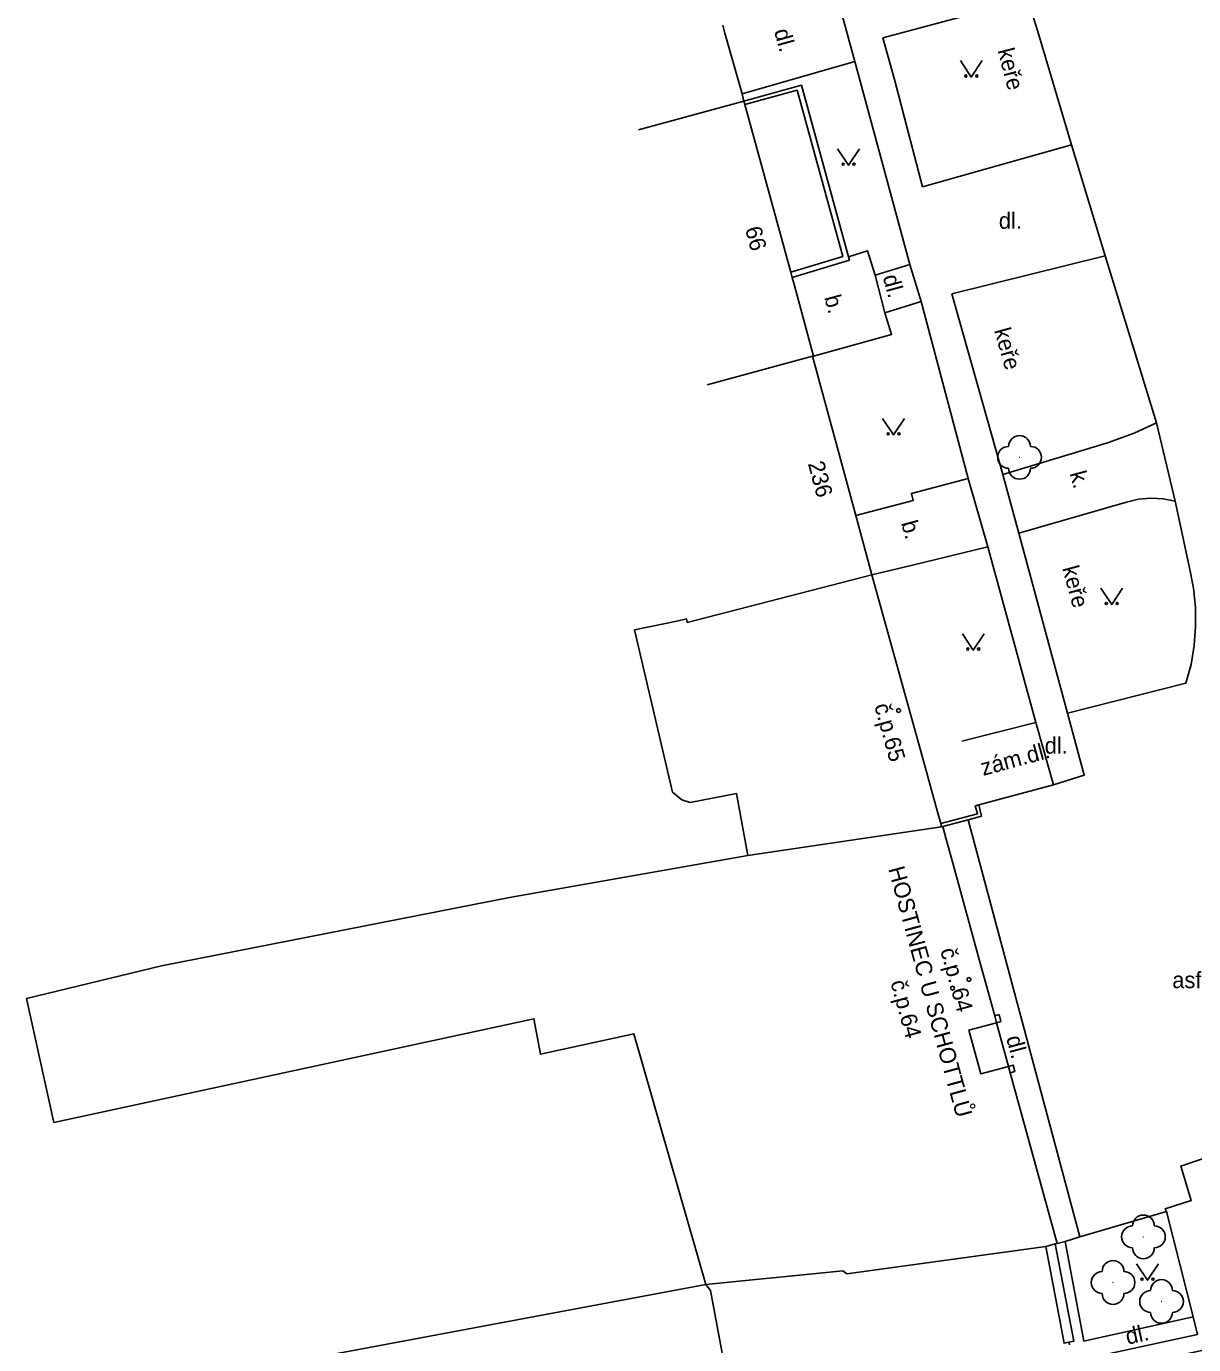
# Model space of a CAD drawing. Extents: x -577457 to -568404, y -1208466 to -1201387.
# Drawn here: x -575435.2 to -575381.8, y -1204135.5 to -1204075.1 of the extents above; entities that cross this region are included whole.
import ezdxf

# ---------------------------------------------------------------- set-up
doc = ezdxf.new("R2010")
doc.units = 0
for name, color, linetype in [('BUDOVY_MĚŘ', 7, 'Continuous'), ('BUDOVY_NEMĚŘ', 7, 'Continuous'), ('POMOC_POPIS', 7, 'Continuous'), ('ROZHRANÍ_PLOCH', 7, 'Continuous'), ('ZELEŇ', 7, 'Continuous'), ('ZN_BUDOV', 7, 'Continuous'), ('ZN_DOPLŇKOVÉ', 7, 'Continuous'), ('ZN_KULTUR', 7, 'Continuous'), ('Č_POPIS_ORIENT', 7, 'Continuous')]:
    doc.layers.add(name, color=color, linetype=linetype)

msp = doc.modelspace()

# ---------------------------------------------------------------- linework, layer by layer
at = {"layer": 'BUDOVY_MĚŘ'}
for points in [[(-575403.21, -1204075.42), (-575403.31, -1204075.05)], [(-575407.17, -1204079.85), (-575402.34, -1204078.53)], [(-575402.43, -1204078.2), (-575402.46, -1204078.09)], [(-575402.34, -1204078.53), (-575402.43, -1204078.2)], [(-575402.3, -1204078.69), (-575402.34, -1204078.53)], [(-575400.2, -1204086.37), (-575402.3, -1204078.69)], [(-575400.13, -1204086.61), (-575400.2, -1204086.37)], [(-575400.06, -1204086.87), (-575400.13, -1204086.61)], [(-575399.15, -1204090.21), (-575399.37, -1204089.42)], [(-575404.02, -1204091.53), (-575399.2, -1204090.22)], [(-575399.2, -1204090.22), (-575399.15, -1204090.21)], [(-575397.22, -1204097.51), (-575399.2, -1204090.22)], [(-575396.48, -1204100.23), (-575396.54, -1204100)], [(-575396.44, -1204100.39), (-575396.48, -1204100.23)], [(-575394.23, -1204108.36), (-575396.44, -1204100.39)], [(-575393.33, -1204111.62), (-575393.48, -1204111.09)], [(-575393.29, -1204111.77), (-575393.33, -1204111.62)], [(-575393.24, -1204111.76), (-575393.29, -1204111.77)], [(-575393.08, -1204112.34), (-575393.24, -1204111.76)], [(-575391.52, -1204118.02), (-575392.75, -1204113.54)], [(-575391.24, -1204119.06), (-575391.52, -1204118.02)], [(-575390.86, -1204120.43), (-575391.24, -1204119.06)], [(-575390.78, -1204120.74), (-575390.86, -1204120.43)], [(-575390.23, -1204122.74), (-575390.78, -1204120.74)], [(-575390.15, -1204123.04), (-575390.23, -1204122.74)], [(-575388, -1204130.85), (-575390.15, -1204123.04)], [(-575388.52, -1204130.99), (-575388.09, -1204130.87)], [(-575388.09, -1204130.87), (-575388, -1204130.85)]]:
    msp.add_lwpolyline(points, dxfattribs=at)
at = {"layer": 'BUDOVY_NEMĚŘ'}
for points in [[(-575405.42, -1204102.35), (-575404.97, -1204102.25), (-575404.94, -1204102.41), (-575396.48, -1204100.23)], [(-575402.17, -1204113.08), (-575402.68, -1204110.25), (-575404.81, -1204110.66), (-575405.19, -1204110.53), (-575405.61, -1204110.19), (-575407.35, -1204102.75), (-575405.42, -1204102.35)], [(-575393.29, -1204111.77), (-575402.17, -1204113.08)], [(-575402.17, -1204113.08), (-575413.08, -1204115.01), (-575429.01, -1204118.14), (-575435.2, -1204119.64), (-575433.94, -1204125.31), (-575411.96, -1204120.56), (-575411.66, -1204122.19), (-575407.38, -1204121.25), (-575404.09, -1204132.73)], [(-575404.09, -1204132.73), (-575397.82, -1204132.1), (-575397.63, -1204132.25), (-575388.52, -1204130.99)], [(-575404.09, -1204132.73), (-575403.88, -1204133.01), (-575402.82, -1204138.65), (-575402.57, -1204140.06), (-575409.22, -1204141.08), (-575409.48, -1204139.36), (-575426.48, -1204142.06), (-575425.1, -1204148.33), (-575429.23, -1204149.24), (-575430.17, -1204145.04), (-575431.67, -1204138.32), (-575427.47, -1204137.4), (-575421.87, -1204136.06), (-575404.09, -1204132.73)]]:
    msp.add_lwpolyline(points, dxfattribs=at)
at = {"layer": 'ROZHRANÍ_PLOCH'}
for points in [[(-575397.26, -1204076.72), (-575398.1, -1204073.63)], [(-575395.98, -1204075.64), (-575389.34, -1204073.85)], [(-575389.34, -1204073.85), (-575388.85, -1204075.45), (-575387.34, -1204080.54)], [(-575394.16, -1204082.46), (-575395.45, -1204077.54), (-575395.98, -1204075.64)], [(-575397.26, -1204076.72), (-575402.43, -1204078.2)], [(-575397.26, -1204076.72), (-575394.75, -1204086.02)], [(-575394.16, -1204082.46), (-575387.34, -1204080.54)], [(-575387.34, -1204080.54), (-575385.8, -1204085.62)], [(-575396.33, -1204086.5), (-575396.69, -1204085.39), (-575397.55, -1204085.66)], [(-575392.82, -1204087.36), (-575385.8, -1204085.62)], [(-575385.8, -1204085.62), (-575383.45, -1204093.27)], [(-575396.33, -1204086.5), (-575394.75, -1204086.02)], [(-575394.75, -1204086.02), (-575394.23, -1204087.71)], [(-575395.89, -1204088.23), (-575396.33, -1204086.5)], [(-575390.49, -1204095.63), (-575392.82, -1204087.36)], [(-575399.15, -1204090.21), (-575395.58, -1204089.22), (-575395.89, -1204088.23)], [(-575395.89, -1204088.23), (-575394.23, -1204087.71)], [(-575394.23, -1204087.71), (-575392.08, -1204095.82)], [(-575383.45, -1204093.27), (-575384.47, -1204093.74), (-575385.52, -1204094.13), (-575385.7, -1204094.19), (-575390.49, -1204095.63)], [(-575383.45, -1204093.27), (-575382.59, -1204096.86)], [(-575392.08, -1204095.82), (-575394.67, -1204096.5), (-575394.59, -1204096.82), (-575397.22, -1204097.51)], [(-575392.08, -1204095.82), (-575391.17, -1204098.94)], [(-575390.49, -1204095.63), (-575389.75, -1204098.32)], [(-575389.75, -1204098.32), (-575384.83, -1204096.9), (-575384.27, -1204096.77), (-575383.71, -1204096.72), (-575383.14, -1204096.75), (-575382.59, -1204096.86)], [(-575387.53, -1204106.56), (-575382.1, -1204105.19), (-575381.87, -1204104.34), (-575381.73, -1204103.47), (-575381.66, -1204102.6), (-575381.67, -1204101.72), (-575381.76, -1204100.84), (-575381.93, -1204099.98), (-575382.59, -1204096.86)], [(-575387.53, -1204106.56), (-575389.75, -1204098.32)], [(-575391.17, -1204098.94), (-575394.62, -1204099.78)], [(-575391.17, -1204098.94), (-575388.98, -1204106.99)], [(-575388.16, -1204109.84), (-575386.76, -1204109.4), (-575387.53, -1204106.56)], [(-575392.37, -1204107.84), (-575388.98, -1204106.99)], [(-575388.98, -1204106.99), (-575388.16, -1204109.84)], [(-575391.59, -1204110.77), (-575388.16, -1204109.84)], [(-575386.96, -1204130.55), (-575392.07, -1204111.45)], [(-575382.99, -1204129.39), (-575383.06, -1204129.27), (-575381.86, -1204128.88), (-575382.34, -1204127.31), (-575380.18, -1204126.58), (-575379.66, -1204128.56)], [(-575382.99, -1204129.39), (-575386.96, -1204130.55)], [(-575382.99, -1204129.39), (-575381.77, -1204134.21)], [(-575387.63, -1204130.76), (-575388, -1204130.85)], [(-575386.96, -1204130.55), (-575387.63, -1204130.76)], [(-575387.63, -1204130.76), (-575386.78, -1204135.32), (-575381.77, -1204134.21)], [(-575381.58, -1204135.02), (-575381.77, -1204134.21)], [(-575381.58, -1204135.02), (-575386.85, -1204136.16), (-575386.69, -1204136.91), (-575381.37, -1204135.75)]]:
    msp.add_lwpolyline(points, dxfattribs=at)
at = {"layer": 'ZELEŇ'}
for centre in [(-575389.72, -1204094.85), (-575384.05, -1204130.55), (-575385.44, -1204132.64), (-575383.22, -1204133.51)]:
    msp.add_circle(centre, 0.0005, dxfattribs=at)
for centre, start, end in [((-575389.72, -1204094.35), 0, 179.99999), ((-575390.22, -1204094.85), 89.99999, 269.99999), ((-575389.22, -1204094.85), 270, 89.99999), ((-575389.72, -1204095.35), 179.99999, 359.99999), ((-575384.05, -1204130.05), 0, 179.99999), ((-575384.55, -1204130.55), 89.99999, 269.99999), ((-575383.55, -1204130.55), 270, 89.99999), ((-575384.05, -1204131.05), 179.99999, 359.99999), ((-575385.44, -1204132.14), 0, 179.99999), ((-575385.94, -1204132.64), 89.99999, 269.99999), ((-575384.94, -1204132.64), 270, 89.99999), ((-575383.22, -1204133.01), 0, 179.99999), ((-575385.44, -1204133.14), 179.99999, 359.99999), ((-575383.72, -1204133.51), 89.99999, 269.99999), ((-575382.72, -1204133.51), 270, 89.99999), ((-575383.22, -1204134.01), 179.99999, 359.99999)]:
    msp.add_arc(centre, 0.5, start, end, dxfattribs=at)
at = {"layer": 'ZN_BUDOV'}
for centre in [(-575395.26, -1204106.44), (-575392.04, -1204118.76), (-575392.79, -1204119.16)]:
    msp.add_circle(centre, 0.0875, dxfattribs=at)
at = {"layer": 'ZN_DOPLŇKOVÉ'}
for points in [[(-575402.46, -1204078.09), (-575403.21, -1204075.42)], [(-575402.34, -1204078.53), (-575399.71, -1204077.81), (-575397.55, -1204085.66)], [(-575402.3, -1204078.69), (-575399.91, -1204078.03), (-575397.82, -1204085.65), (-575400.2, -1204086.37)], [(-575397.55, -1204085.66), (-575397.51, -1204085.82), (-575400.13, -1204086.61)], [(-575399.37, -1204089.42), (-575400.06, -1204086.87)], [(-575396.54, -1204100), (-575397.22, -1204097.51)], [(-575396.48, -1204100.23), (-575394.62, -1204099.78)], [(-575393.48, -1204111.09), (-575394.23, -1204108.36)], [(-575391.59, -1204110.77), (-575391.75, -1204110.81), (-575391.65, -1204111.17), (-575393.33, -1204111.62)], [(-575392.07, -1204111.45), (-575391.46, -1204111.28), (-575391.59, -1204110.77)], [(-575393.24, -1204111.76), (-575392.07, -1204111.45)], [(-575392.75, -1204113.54), (-575393.08, -1204112.34)], [(-575390.23, -1204122.74), (-575391.5, -1204123.09), (-575392.05, -1204121.08), (-575390.78, -1204120.74)], [(-575390.86, -1204120.43), (-575390.66, -1204120.37), (-575390.58, -1204120.68), (-575390.78, -1204120.74)], [(-575390.23, -1204122.74), (-575390.01, -1204122.68), (-575389.93, -1204122.98), (-575390.15, -1204123.04)], [(-575387.46, -1204135.37), (-575387.68, -1204135.42), (-575388.52, -1204130.99)], [(-575388.09, -1204130.87), (-575387.24, -1204135.33), (-575387.46, -1204135.37)], [(-575387.46, -1204135.37), (-575387.43, -1204135.5)]]:
    msp.add_lwpolyline(points, dxfattribs=at)
at = {"layer": 'ZN_KULTUR'}
for points in [[(-575392.43, -1204076.68), (-575391.93, -1204077.43), (-575391.43, -1204076.68)], [(-575398.05, -1204080.72), (-575397.55, -1204081.47), (-575397.05, -1204080.72)], [(-575395.99, -1204093.07), (-575395.49, -1204093.82), (-575394.99, -1204093.07)], [(-575386, -1204100.84), (-575385.5, -1204101.59), (-575385, -1204100.84)], [(-575392.34, -1204102.93), (-575391.84, -1204103.68), (-575391.34, -1204102.93)], [(-575384.36, -1204131.79), (-575383.86, -1204132.54), (-575383.36, -1204131.79)]]:
    msp.add_lwpolyline(points, dxfattribs=at)
for centre in [(-575392.18, -1204077.38), (-575391.68, -1204077.38), (-575397.8, -1204081.42), (-575397.3, -1204081.42), (-575395.74, -1204093.77), (-575395.24, -1204093.77), (-575385.75, -1204101.54), (-575385.25, -1204101.54), (-575392.09, -1204103.63), (-575391.59, -1204103.63), (-575384.11, -1204132.49), (-575383.61, -1204132.49)]:
    msp.add_circle(centre, 0.05, dxfattribs=at)

# ---------------------------------------------------------------- texts
at = {"layer": 'POMOC_POPIS'}
for s, rotation, p in [('dl.', 285.48997, (-575400.97, -1204075.32)), ('dl.', 285.29998, (-575395.99, -1204086.58)), ('b.', 285.29998, (-575398.67, -1204087.52)), ('k.', 285.27998, (-575387.43, -1204095.58)), ('b.', 285.18, (-575395.15, -1204097.85)), ('zám.dl.', 15.17026, (-575391.39, -1204109.44)), ('HOSTINEC U SCHOTTLŮ', 285.33997, (-575395.74, -1204113.69)), ('dl.', 284.97809, (-575390.34, -1204121.43)), ('dl.', 12.20606, (-575384.78, -1204135.49))]:
    msp.add_text(s, height=0.75, rotation=rotation, dxfattribs=at).set_placement(p)
for s, p in [('dl.', (-575390.67, -1204084.38)), ('dl.', (-575388.57, -1204108.42)), ('asfalt', (-575382.73, -1204119.16))]:
    msp.add_text(s, height=0.75, dxfattribs=at).set_placement(p)
at = {"layer": 'ZELEŇ'}
for rotation, p in [(284.69196, (-575390.73, -1204076.21)), (285.73474, (-575390.89, -1204089.03)), (285.07847, (-575387.77, -1204099.92))]:
    msp.add_text('keře', height=0.75, rotation=rotation, dxfattribs=at).set_placement(p)
at = {"layer": 'Č_POPIS_ORIENT'}
for s, rotation, p in [('66', 285.29998, (-575402.3, -1204084.38)), ('236', 285.18, (-575399.42, -1204095.13)), ('č.p.65', 285.44001, (-575396.38, -1204106.22)), ('č.p. 64', 285.35246, (-575393.36, -1204117.42)), ('č.p.64', 285.35246, (-575395.64, -1204118.89))]:
    msp.add_text(s, height=0.75, rotation=rotation, dxfattribs=at).set_placement(p)

doc.saveas('drawing.dxf')
